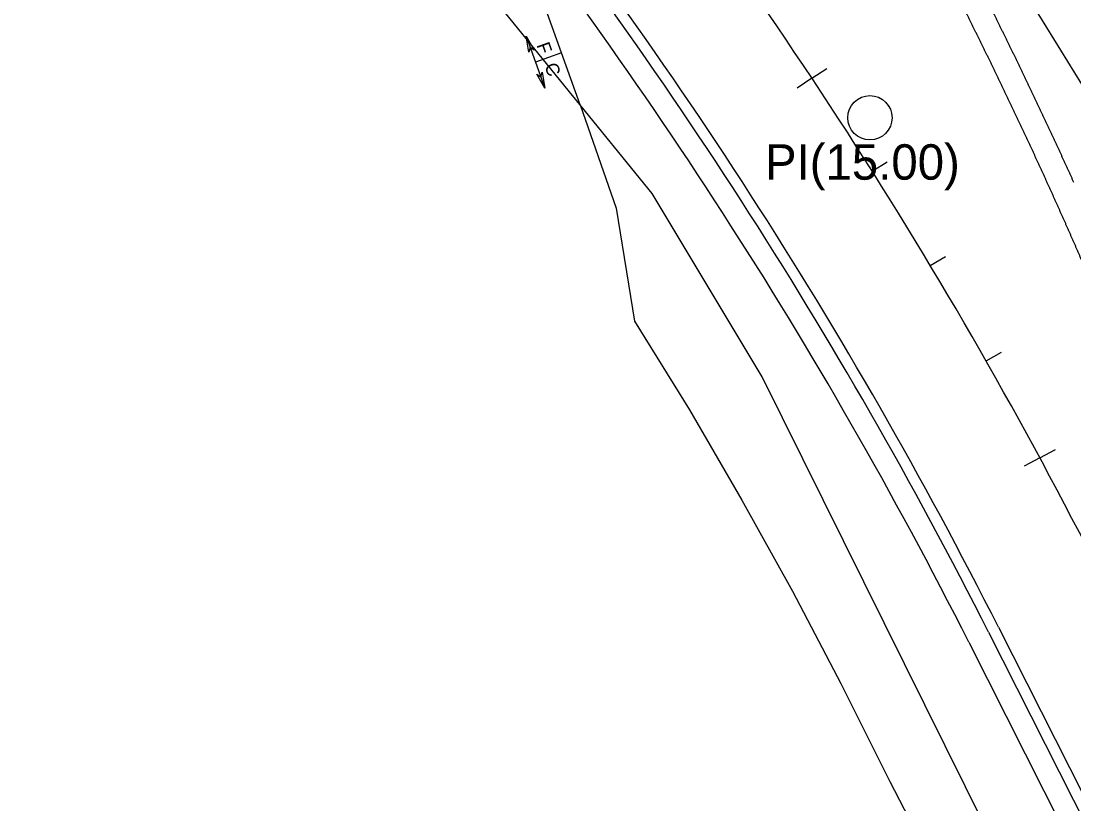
# Model space of a CAD drawing. Extents: x 2717836 to 2719883, y 337327 to 339806.
# Drawn here: x 2718281.9 to 2718519.7, y 338862.7 to 339039.5 of the extents above; entities that cross this region are included whole.
import ezdxf

# ---------------------------------------------------------------- set-up
doc = ezdxf.new("R2010")
doc.units = 0
for name, color, linetype in [('Level 1', 7, 'Continuous'), ('Level 22', 7, 'Continuous'), ('Level 23', 7, 'Continuous'), ('Level 31', 7, 'Continuous'), ('Level 4', 7, 'Continuous'), ('Level 52', 7, 'Continuous'), ('Level 7', 7, 'Continuous')]:
    doc.layers.add(name, color=color, linetype=linetype)

msp = doc.modelspace()

# ---------------------------------------------------------------- linework, layer by layer
at = {"layer": 'Level 1'}
msp.add_arc((2717543.97, 338418.37), 1100, 26.79977, 38.81809, dxfattribs=at)
at = {"layer": 'Level 22'}
for p, q in [((2718403.98, 339032.34), (2718399.78, 339044.1)), ((2718408.18, 339020.58), (2718403.98, 339032.34)), ((2718408.18, 339020.58), (2718416.3, 338997.25)), ((2718416.3, 338997.25), (2718420.43, 338971.72)), ((2718420.43, 338971.72), (2718432.85, 338951.7)), ((2718432.85, 338951.7), (2718444.68, 338931.33)), ((2718444.68, 338931.33), (2718456.14, 338910.75)), ((2718456.14, 338910.75), (2718467.03, 338889.86)), ((2718467.03, 338889.86), (2718478.12, 338867.77)), ((2718478.12, 338867.77), (2718489.58, 338845.55))]:
    msp.add_line(p, q, dxfattribs=at)
at = {"layer": 'Level 23'}
for p, q in [((2718424.43, 339000.58), (2718281.94, 339176.11)), ((2718449.26, 338959.14), (2718424.43, 339000.58)), ((2718625.84, 338603.02), (2718449.26, 338959.14))]:
    msp.add_line(p, q, dxfattribs=at)
msp.add_arc((2717727.19, 338544.44), 928.46, 26.92138, 38.79718, dxfattribs=at)
at = {"layer": 'Level 31'}
for p, q in [((2718460.52, 339026.59), (2718463.86, 339028.8)), ((2718460.52, 339026.59), (2718457.19, 339024.38)), ((2718474.11, 339005.61), (2718477.49, 339007.74)), ((2718487.21, 338984.32), (2718490.64, 338986.37)), ((2718499.83, 338962.74), (2718503.31, 338964.71)), ((2718511.96, 338940.87), (2718515.48, 338942.77)), ((2718511.96, 338940.87), (2718508.44, 338938.97))]:
    msp.add_line(p, q, dxfattribs=at)
msp.add_circle((2718473.61, 339017.69), 5, dxfattribs=at)
at = {"layer": 'Level 4'}
msp.add_line((2718502.61, 338902.61), (2718534.11, 338840.26), dxfattribs=at)
msp.add_arc((2717543.97, 338418.37), 1074, 26.79977, 38.81809, dxfattribs=at)
for points in [[(2718514.65, 339000.78), (2718514.36, 339001.42), (2718514.08, 339002.06), (2718513.79, 339002.7), (2718513.5, 339003.33), (2718513.21, 339003.97), (2718512.92, 339004.6), (2718512.63, 339005.24), (2718512.33, 339005.88), (2718512.04, 339006.52), (2718511.75, 339007.16), (2718511.46, 339007.79), (2718511.16, 339008.43), (2718510.87, 339009.06), (2718510.58, 339009.7), (2718510.28, 339010.34), (2718509.99, 339010.97), (2718509.69, 339011.61), (2718509.4, 339012.24), (2718509.1, 339012.88), (2718508.81, 339013.51), (2718508.51, 339014.15), (2718508.21, 339014.78), (2718507.91, 339015.42), (2718507.61, 339016.06), (2718507.32, 339016.69), (2718507.02, 339017.32), (2718506.72, 339017.95), (2718506.42, 339018.59), (2718506.12, 339019.22), (2718505.82, 339019.86), (2718505.52, 339020.5), (2718505.22, 339021.12), (2718504.91, 339021.76), (2718504.61, 339022.39), (2718504.31, 339023.03), (2718504.01, 339023.65), (2718503.7, 339024.29), (2718503.4, 339024.93), (2718503.1, 339025.56), (2718502.79, 339026.19), (2718502.49, 339026.82), (2718502.18, 339027.45), (2718501.88, 339028.08), (2718501.57, 339028.72), (2718501.26, 339029.35), (2718500.95, 339029.98), (2718500.64, 339030.61), (2718500.34, 339031.24), (2718500.03, 339031.88), (2718499.72, 339032.5), (2718499.41, 339033.14), (2718499.1, 339033.77), (2718498.79, 339034.4), (2718498.48, 339035.03), (2718498.17, 339035.66), (2718497.86, 339036.29), (2718497.55, 339036.91), (2718497.24, 339037.55), (2718496.93, 339038.17), (2718496.61, 339038.81), (2718496.3, 339039.44), (2718495.98, 339040.06), (2718495.67, 339040.7), (2718495.36, 339041.32), (2718495.04, 339041.95), (2718494.73, 339042.58), (2718494.41, 339043.21), (2718494.09, 339043.84), (2718493.78, 339044.46), (2718493.46, 339045.1), (2718493.14, 339045.72), (2718492.82, 339046.35), (2718492.19, 339047.6)], [(2718534.83, 338953.22), (2718534.58, 338953.87), (2718534.32, 338954.52), (2718534.06, 338955.17), (2718533.8, 338955.81), (2718533.54, 338956.46), (2718533.29, 338957.1), (2718533.02, 338957.75), (2718532.76, 338958.4), (2718532.5, 338959.04), (2718532.24, 338959.69), (2718531.98, 338960.33), (2718531.72, 338960.98), (2718531.46, 338961.62), (2718531.19, 338962.27), (2718530.93, 338962.92), (2718530.67, 338963.56), (2718530.4, 338964.21), (2718530.14, 338964.85), (2718529.87, 338965.5), (2718529.61, 338966.14), (2718529.34, 338966.79), (2718529.08, 338967.43), (2718528.81, 338968.08), (2718528.54, 338968.72), (2718528.27, 338969.36), (2718528, 338970.01), (2718527.74, 338970.65), (2718527.47, 338971.3), (2718527.2, 338971.94), (2718526.93, 338972.58), (2718526.66, 338973.23), (2718526.39, 338973.87), (2718526.12, 338974.52), (2718525.85, 338975.16), (2718525.58, 338975.8), (2718525.31, 338976.44), (2718525.03, 338977.09), (2718524.76, 338977.73), (2718524.49, 338978.37), (2718524.21, 338979.02), (2718523.94, 338979.65), (2718523.66, 338980.3), (2718523.39, 338980.94), (2718523.11, 338981.58), (2718522.83, 338982.23), (2718522.56, 338982.87), (2718522.28, 338983.51), (2718522.01, 338984.15), (2718521.73, 338984.79), (2718521.45, 338985.43), (2718521.17, 338986.07), (2718520.89, 338986.72), (2718520.61, 338987.35), (2718520.33, 338988), (2718520.06, 338988.63), (2718519.77, 338989.28), (2718519.49, 338989.91), (2718519.21, 338990.56), (2718518.93, 338991.19), (2718518.65, 338991.84), (2718518.36, 338992.48), (2718518.08, 338993.11), (2718517.8, 338993.76), (2718517.52, 338994.39), (2718517.23, 338995.03), (2718516.95, 338995.67), (2718516.66, 338996.31), (2718516.37, 338996.95), (2718516.09, 338997.59), (2718515.8, 338998.23), (2718515.52, 338998.86), (2718515.23, 338999.51), (2718514.94, 339000.14), (2718514.65, 339000.78)]]:
    msp.add_spline(points, degree=3, dxfattribs=at)
at = {"layer": 'Level 52'}
for p, q in [((2718395.99, 339036.12), (2718400.19, 339024.35)), ((2718403.98, 339032.34), (2718398.09, 339030.24))]:
    msp.add_line(p, q, dxfattribs=at)
for points in [[(2718395.99, 339036.12), (2718397.77, 339032.94), (2718396.89, 339033.58), (2718396.61, 339032.52)], [(2718400.19, 339024.35), (2718398.41, 339027.54), (2718399.29, 339026.9), (2718399.57, 339027.96)]]:
    msp.add_lwpolyline(points, close=True, dxfattribs=at)
at = {"layer": 'Level 7'}
for p, q in [((2718500.38, 338901.48), (2718531.88, 338839.13)), ((2718495.92, 338899.23), (2718527.41, 338836.88))]:
    msp.add_line(p, q, dxfattribs=at)
for radius in [1071.5, 1066.5]:
    msp.add_arc((2717543.97, 338418.37), radius, 26.79977, 38.81809, dxfattribs=at)
msp.add_spline([(2718519.66, 339003.05), (2718519.37, 339003.69), (2718519.09, 339004.33), (2718518.79, 339004.97), (2718518.5, 339005.61), (2718518.21, 339006.25), (2718517.92, 339006.89), (2718517.63, 339007.53), (2718517.33, 339008.17), (2718517.04, 339008.81), (2718516.75, 339009.45), (2718516.46, 339010.09), (2718516.16, 339010.73), (2718515.87, 339011.36), (2718515.57, 339012.01), (2718515.27, 339012.65), (2718514.98, 339013.28), (2718514.68, 339013.93), (2718514.39, 339014.56), (2718514.09, 339015.2), (2718513.79, 339015.84), (2718513.49, 339016.48), (2718513.19, 339017.11), (2718512.89, 339017.76), (2718512.59, 339018.39), (2718512.29, 339019.03), (2718511.99, 339019.67), (2718511.69, 339020.3), (2718511.39, 339020.94), (2718511.09, 339021.57), (2718510.79, 339022.22), (2718510.48, 339022.85), (2718510.18, 339023.49), (2718509.88, 339024.13), (2718509.58, 339024.76), (2718509.27, 339025.4), (2718508.97, 339026.03), (2718508.66, 339026.67), (2718508.35, 339027.31), (2718508.05, 339027.94), (2718507.74, 339028.58), (2718507.44, 339029.21), (2718507.13, 339029.85), (2718506.83, 339030.48), (2718506.52, 339031.12), (2718506.21, 339031.76), (2718505.9, 339032.39), (2718505.59, 339033.02), (2718505.28, 339033.65), (2718504.97, 339034.29), (2718504.66, 339034.92), (2718504.35, 339035.56), (2718504.04, 339036.2), (2718503.73, 339036.82), (2718503.41, 339037.46), (2718503.1, 339038.09), (2718502.79, 339038.73), (2718502.48, 339039.35), (2718502.16, 339039.99), (2718501.85, 339040.62), (2718501.53, 339041.26), (2718501.22, 339041.89), (2718500.91, 339042.52), (2718500.59, 339043.16), (2718500.27, 339043.78), (2718499.96, 339044.42), (2718499.64, 339045.04), (2718499.32, 339045.68), (2718499, 339046.32), (2718498.69, 339046.94), (2718498.37, 339047.58), (2718498.05, 339048.2), (2718497.73, 339048.84), (2718497.09, 339050.09)], degree=3, dxfattribs=at)

# ---------------------------------------------------------------- texts
at = {"layer": 'Level 31'}
msp.add_text('PI(15.00)', height=8, dxfattribs=at).set_placement((2718449.9, 339003.69))
at = {"layer": 'Level 52'}
for s, p in [('F', (2718398.28, 339034.11)), ('C', (2718400.08, 339029.46))]:
    msp.add_text(s, height=3, rotation=289.6542, dxfattribs=at).set_placement(p)

doc.saveas('drawing.dxf')
